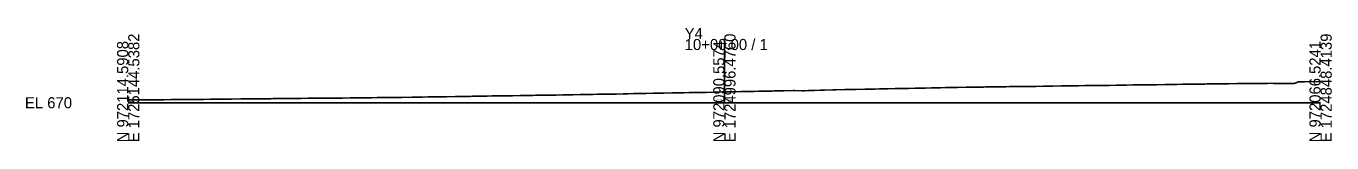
# Model space of a CAD drawing. Extents: x -26 to 303, y -10 to 3046.
# Drawn here: x -25.7 to 302.8, y -9.7 to 18.9 of the extents above; entities that cross this region are included whole.
import ezdxf

# ---------------------------------------------------------------- set-up
doc = ezdxf.new("R2010")
doc.units = 0
for name, color, linetype in [('Default', 7, 'Continuous'), ('Exist Cross Section Cell', 7, 'Continuous'), ('Exist XS Center Line Elevation Label', 7, 'Continuous'), ('Exist XS Ground Line', 7, 'Continuous')]:
    doc.layers.add(name, color=color, linetype=linetype)

msp = doc.modelspace()

# ---------------------------------------------------------------- linework, layer by layer
at = {"layer": 'Exist Cross Section Cell'}
for p, q in [((150, 0), (150, 16.12)), ((0, 0), (150, 0)), ((150, 0), (300, 0))]:
    msp.add_line(p, q, dxfattribs=at)
at = {"layer": 'Exist XS Ground Line'}
msp.add_lwpolyline([(0, 0.7), (0.45, 0.7), (1.81, 0.71), (2.98, 0.72), (4.85, 0.74), (5.51, 0.75), (5.99, 0.75), (8.19, 0.77), (9.06, 0.78), (10.86, 0.8), (13.11, 0.82), (13.88, 0.82), (15.65, 0.84), (16.95, 0.85), (18.18, 0.86), (19.06, 0.86), (20.71, 0.88), (21.27, 0.88), (23.46, 0.9), (24.74, 0.91), (25.99, 0.92), (28.32, 0.95), (29.96, 0.96), (30.84, 0.97), (32.17, 0.99), (33.38, 1), (35.09, 1.02), (35.91, 1.03), (36.5, 1.04), (38.68, 1.07), (40.24, 1.08), (41.11, 1.09), (43.51, 1.1), (45.21, 1.12), (46.05, 1.12), (47.41, 1.13), (48.57, 1.14), (50.22, 1.16), (51.11, 1.17), (51.75, 1.18), (53.64, 1.2), (53.94, 1.2), (55.8, 1.22), (56.25, 1.22), (58.7, 1.25), (60.47, 1.27), (61.23, 1.28), (62.65, 1.3), (63.77, 1.31), (65.32, 1.33), (66.3, 1.34), (67, 1.35), (68.84, 1.37), (71.36, 1.4), (73.33, 1.43), (73.92, 1.44), (75.39, 1.46), (76.45, 1.47), (76.77, 1.47), (77.84, 1.49), (79.44, 1.51), (80.06, 1.52), (82.3, 1.56), (83.56, 1.58), (84.53, 1.59), (86.01, 1.62), (86.63, 1.63), (87.12, 1.63), (87.54, 1.64), (89.1, 1.67), (89.57, 1.67), (90.33, 1.68), (91.62, 1.71), (93.14, 1.73), (94.17, 1.75), (95.33, 1.77), (96.69, 1.79), (98.59, 1.82), (99.22, 1.83), (99.67, 1.84), (101.76, 1.87), (102.45, 1.88), (104.28, 1.91), (106.21, 1.94), (106.82, 1.95), (107.65, 1.96), (109.34, 1.99), (110.68, 2.01), (111.89, 2.03), (113.71, 2.06), (114.41, 2.07), (116.97, 2.12), (118.03, 2.13), (119.74, 2.16), (122.03, 2.2), (122.79, 2.21), (124.53, 2.25), (125.8, 2.27), (127.1, 2.3), (128.03, 2.32), (129.62, 2.34), (130.19, 2.35), (132.14, 2.39), (133.62, 2.42), (134.68, 2.44), (136.73, 2.49), (137.21, 2.5), (137.88, 2.51), (139.74, 2.54), (141.09, 2.57), (142.28, 2.58), (143.92, 2.61), (144.8, 2.62), (145.43, 2.63), (147.34, 2.67), (149.53, 2.72), (150, 2.73), (152.41, 2.78), (154.18, 2.82), (154.95, 2.83), (156.35, 2.86), (157.47, 2.88), (158.56, 2.9), (160.01, 2.93), (162.05, 2.97), (162.54, 2.98), (165.07, 3.01), (167.26, 3.06), (167.61, 3.07), (169.44, 3.05), (170.14, 3.05), (171.1, 3.08), (172.67, 3.12), (174.13, 3.14), (175.2, 3.16), (177.19, 3.24), (177.75, 3.27), (178.15, 3.28), (180.28, 3.33), (180.72, 3.34), (182.79, 3.38), (183.19, 3.38), (185.35, 3.43), (186.25, 3.44), (187.87, 3.47), (189.05, 3.49), (190.4, 3.52), (191.24, 3.54), (192.95, 3.58), (195.46, 3.63), (196.31, 3.64), (198, 3.68), (199.94, 3.71), (200.54, 3.72), (202.13, 3.75), (203.06, 3.77), (204.4, 3.8), (205.61, 3.83), (206.49, 3.84), (208.12, 3.87), (208.65, 3.88), (210.85, 3.92), (211.89, 3.94), (213.2, 3.96), (215.18, 3.98), (215.73, 3.99), (217.38, 4.01), (218.27, 4.02), (219.51, 4.04), (220.79, 4.06), (221.71, 4.07), (223.34, 4.08), (223.92, 4.09), (225.87, 4.12), (227.42, 4.14), (228.42, 4.15), (230.3, 4.18), (231.11, 4.2), (231.41, 4.2), (232.62, 4.22), (234.69, 4.25), (235.29, 4.26), (236.8, 4.27), (237.57, 4.28), (238.98, 4.3), (240.7, 4.33), (241.23, 4.33), (242.89, 4.35), (243.73, 4.36), (246.15, 4.39), (246.77, 4.4), (248.67, 4.43), (249.78, 4.44), (251.18, 4.47), (252.78, 4.49), (253.7, 4.5), (255.79, 4.53), (256.23, 4.53), (258.75, 4.57), (260.88, 4.62), (261.29, 4.62), (263.09, 4.63), (263.84, 4.64), (265.27, 4.66), (266.37, 4.67), (267.45, 4.68), (268.9, 4.7), (270.87, 4.74), (271.41, 4.75), (274.14, 4.78), (276.17, 4.81), (276.5, 4.81), (276.94, 4.82), (279, 4.84), (279.99, 4.85), (281.56, 4.86), (283, 4.87), (284.09, 4.88), (286.31, 4.9), (286.63, 4.9), (287.46, 4.91), (288.15, 4.9), (288.82, 4.89), (290.95, 4.87), (293.38, 4.85), (294.44, 5.26), (295.96, 5.28), (300, 5.37)], dxfattribs=at)

# ---------------------------------------------------------------- texts
at = {"layer": 'Default'}
msp.add_text('-', height=0.0001, dxfattribs=at).set_placement((0, 0))
at = {"layer": 'Exist Cross Section Cell'}
for s, p in [('E 1725144.5382', (2.8, -10)), ('E 1724996.4760', (152.8, -10)), ('E 1724848.4139', (302.8, -10)), ('N 972114.5908', (0, -10)), ('N 972090.5574', (150, -10)), ('N 972066.5241', (300, -10))]:
    msp.add_text(s, height=2.8, rotation=90, dxfattribs=at).set_placement(p)
for s, p in [('Y4', (140, 16.12)), ('10+00.00 / 1', (140, 13.32)), ('EL 670', (-26, -1.4))]:
    msp.add_text(s, height=2.8, dxfattribs=at).set_placement(p)
at = {"layer": 'Exist XS Center Line Elevation Label'}
msp.add_text('672.73', height=1, dxfattribs=at).set_placement((147.85, -0.2))

doc.saveas('drawing.dxf')
